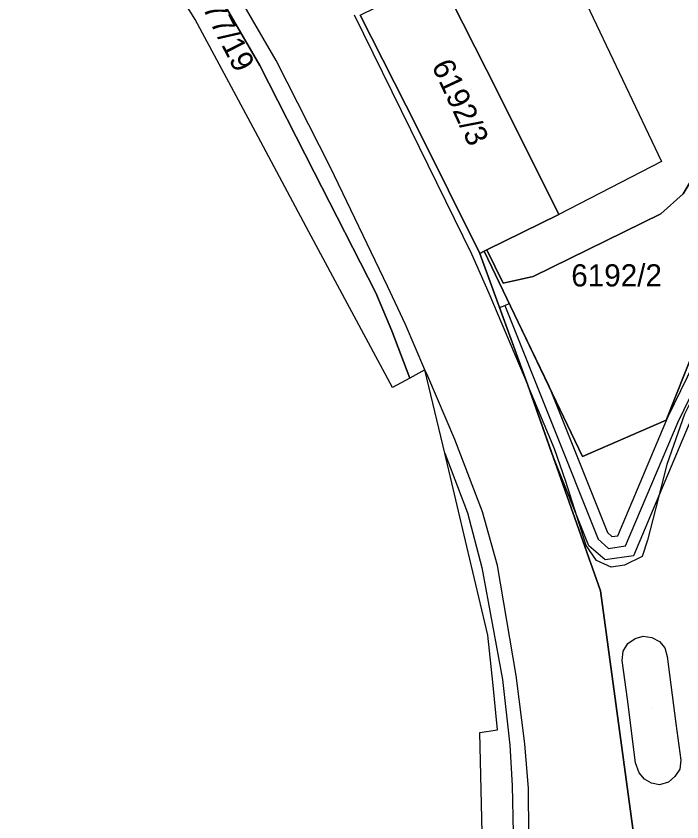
# Model space of a CAD drawing. Extents: x -266199 to -261993, y -1239047 to -1235108.
# Drawn here: x -264045.7 to -263985.6, y -1235963.6 to -1235890.9 of the extents above; entities that cross this region are included whole.
import ezdxf

# ---------------------------------------------------------------- set-up
doc = ezdxf.new("R2010")
doc.units = 0
for name, color, linetype in [('body_kn', 7, 'Continuous'), ('katuz_linie', 7, 'Continuous'), ('kladpar_druhypozemkov', 7, 'Continuous'), ('kladpar_hranice', 7, 'Continuous'), ('kladpar_parcelnecisla', 7, 'Continuous'), ('kladpar_plochy', 7, 'Continuous'), ('tarchy_linie', 7, 'Continuous'), ('zappar_hrandruhpozemk', 7, 'Continuous'), ('zuob_linie', 7, 'Continuous'), ('zuob_plochy', 7, 'Continuous')]:
    doc.layers.add(name, color=color, linetype=linetype)

msp = doc.modelspace()

# ---------------------------------------------------------------- linework, layer by layer
at = {"layer": 'body_kn'}
for p, q in [((-264029.57, -1235891.15), (-264029.57, -1235891.15)), ((-264023.75, -1235895.3), (-264023.75, -1235895.3)), ((-264022.25, -1235894.85), (-264022.25, -1235894.85)), ((-264002.2, -1235897.83), (-264002.2, -1235897.83)), ((-264010.15, -1235901.08), (-264010.15, -1235901.08)), ((-264009.53, -1235900.91), (-264009.53, -1235900.91)), ((-264024.13, -1235901.29), (-264024.13, -1235901.29)), ((-263987.47, -1235903.97), (-263987.47, -1235903.97)), ((-264017.36, -1235904.51), (-264017.36, -1235904.51)), ((-264018.82, -1235904.93), (-264018.82, -1235904.93)), ((-263996.74, -1235908.75), (-263996.74, -1235908.75)), ((-263996.74, -1235908.75), (-263996.74, -1235908.75)), ((-263987.53, -1235908.7), (-263987.53, -1235908.7)), ((-264019.3, -1235910.3), (-264019.3, -1235910.3)), ((-264003.25, -1235911.94), (-264003.25, -1235911.94)), ((-264003.25, -1235911.94), (-264003.25, -1235911.94)), ((-264004.64, -1235912.3), (-264004.64, -1235912.3)), ((-264003.88, -1235912.26), (-264003.88, -1235912.26)), ((-264003.88, -1235912.26), (-264003.88, -1235912.26)), ((-264003.48, -1235912.06), (-264003.48, -1235912.06)), ((-264003.48, -1235912.06), (-264003.48, -1235912.06)), ((-264001.76, -1235914.93), (-264001.76, -1235914.93)), ((-263999.06, -1235914.35), (-263999.06, -1235914.35)), ((-264012.21, -1235915.22), (-264012.21, -1235915.22)), ((-264013.28, -1235915.83), (-264013.28, -1235915.83)), ((-264003.07, -1235915.84), (-264003.07, -1235915.84)), ((-264001.62, -1235916.97), (-264001.62, -1235916.97)), ((-264001.62, -1235916.97), (-264001.62, -1235916.97)), ((-264001.22, -1235916.78), (-264001.22, -1235916.78)), ((-264001.22, -1235916.78), (-264001.22, -1235916.78)), ((-264002.1, -1235917.15), (-264002.1, -1235917.15)), ((-264011.83, -1235919.25), (-264011.83, -1235919.25)), ((-264010.6, -1235918.68), (-264010.6, -1235918.68)), ((-264008.83, -1235922.76), (-264008.83, -1235922.76)), ((-264010.21, -1235923.51), (-264010.21, -1235923.51)), ((-264010.21, -1235923.51), (-264010.21, -1235923.51)), ((-264008.56, -1235923.35), (-264008.56, -1235923.35)), ((-264011.76, -1235924.36), (-264011.76, -1235924.36)), ((-263999.56, -1235924.14), (-263999.56, -1235924.14)), ((-263997.66, -1235924.21), (-263997.66, -1235924.21)), ((-263986.9, -1235927.03), (-263986.9, -1235927.03)), ((-263987.05, -1235927.32), (-263987.05, -1235927.32)), ((-263985.99, -1235927.45), (-263985.99, -1235927.45)), ((-264006.14, -1235929.04), (-264006.14, -1235929.04)), ((-263997.44, -1235930.13), (-263997.44, -1235930.13)), ((-263997.15, -1235929.88), (-263997.15, -1235929.88)), ((-264007.04, -1235930.29), (-264007.04, -1235930.29)), ((-264007.04, -1235930.29), (-264007.04, -1235930.29)), ((-263994.6, -1235930.59), (-263994.6, -1235930.59)), ((-263987.01, -1235931.31), (-263987.01, -1235931.31)), ((-263996.11, -1235932.85), (-263996.11, -1235932.85)), ((-263987.98, -1235935.23), (-263987.98, -1235935.23)), ((-264005, -1235935.66), (-264005, -1235935.66)), ((-264003.63, -1235935.59), (-264003.63, -1235935.59)), ((-263995.11, -1235935.97), (-263995.11, -1235935.97)), ((-263992.36, -1235937.45), (-263992.36, -1235937.45)), ((-263993.2, -1235938.05), (-263993.2, -1235938.05)), ((-263991.95, -1235937.81), (-263991.95, -1235937.81)), ((-263991.42, -1235937.73), (-263991.42, -1235937.73)), ((-263988.74, -1235938.14), (-263988.74, -1235938.14)), ((-264005.04, -1235938.71), (-264005.04, -1235938.71)), ((-263994.28, -1235938.6), (-263994.28, -1235938.6)), ((-263994.04, -1235938.64), (-263994.04, -1235938.64)), ((-263992.27, -1235938.87), (-263992.27, -1235938.87)), ((-263990.72, -1235938.64), (-263990.72, -1235938.64)), ((-263990.01, -1235939.54), (-263990.01, -1235939.54)), ((-263989.22, -1235939.6), (-263989.22, -1235939.6)), ((-263993.36, -1235939.96), (-263993.36, -1235939.96)), ((-263992.58, -1235939.92), (-263992.58, -1235939.92)), ((-263990.81, -1235940.38), (-263990.81, -1235940.38)), ((-264003.71, -1235940.6), (-264003.71, -1235940.6)), ((-264002.28, -1235940.41), (-264002.28, -1235940.41)), ((-263992.02, -1235940.57), (-263992.02, -1235940.57)), ((-263993, -1235942.71), (-263993, -1235942.71)), ((-264003.15, -1235946.69), (-264003.15, -1235946.69)), ((-263989.13, -1235946.79), (-263989.13, -1235946.79)), ((-263988.36, -1235946.91), (-263988.36, -1235946.91)), ((-263990.53, -1235947.46), (-263990.53, -1235947.46)), ((-263989.87, -1235946.99), (-263989.87, -1235946.99)), ((-263987.66, -1235947.28), (-263987.66, -1235947.28)), ((-263990.93, -1235948.14), (-263990.93, -1235948.14)), ((-263987.19, -1235947.86), (-263987.19, -1235947.86)), ((-263991.03, -1235948.98), (-263991.03, -1235948.98)), ((-263986.96, -1235948.62), (-263986.96, -1235948.62)), ((-263986.96, -1235948.62), (-263986.96, -1235948.62)), ((-264000.6, -1235950.35), (-264000.6, -1235950.35)), ((-264002.71, -1235950.93), (-264002.71, -1235950.93)), ((-264001.84, -1235950.69), (-264001.84, -1235950.69)), ((-263990.55, -1235952.48), (-263990.55, -1235952.48)), ((-263986.2, -1235954.66), (-263986.2, -1235954.66)), ((-264003.87, -1235955.49), (-264003.87, -1235955.49)), ((-264002.27, -1235955.24), (-264002.27, -1235955.24)), ((-264001.16, -1235956.64), (-264001.16, -1235956.64)), ((-263999.83, -1235956.51), (-263999.83, -1235956.51)), ((-263989.82, -1235958.23), (-263989.82, -1235958.23)), ((-263985.75, -1235957.99), (-263985.75, -1235957.99)), ((-263989.5, -1235959.12), (-263989.5, -1235959.12)), ((-263985.84, -1235958.78), (-263985.84, -1235958.78)), ((-263989.01, -1235959.71), (-263989.01, -1235959.71)), ((-263986.85, -1235959.97), (-263986.85, -1235959.97)), ((-263986.27, -1235959.45), (-263986.27, -1235959.45)), ((-264000.95, -1235960.27), (-264000.95, -1235960.27)), ((-263999.49, -1235960.54), (-263999.49, -1235960.54)), ((-263988.39, -1235960.07), (-263988.39, -1235960.07)), ((-263987.66, -1235960.21), (-263987.66, -1235960.21))]:
    msp.add_line(p, q, dxfattribs=at)
at = {"layer": 'katuz_linie'}
msp.add_lwpolyline([(-264003.46, -1235973.59), (-264003.87, -1235955.49), (-264002.27, -1235955.24), (-264002.71, -1235950.93), (-264003.15, -1235946.69), (-264005.04, -1235938.71), (-264007.04, -1235930.29), (-264008.83, -1235922.76), (-264010.21, -1235923.51), (-264011.76, -1235924.36), (-264019.3, -1235910.3), (-264024.13, -1235901.29), (-264029.57, -1235891.15), (-264042.7, -1235869.88), (-264048.1, -1235861.33), (-264049.44, -1235859.21), (-264053.95, -1235852.08), (-264058.96, -1235845.12), (-264074.52, -1235819.37), (-264076.7, -1235814.88), (-264087.74, -1235792.21), (-264102.26, -1235766.16)], dxfattribs=at)
at = {"layer": 'kladpar_druhypozemkov'}
for p, q in [((-264004.59, -1235897.48), (-264004.59, -1235897.48)), ((-263990.87, -1235913.71), (-263990.87, -1235913.71)), ((-263988.31, -1235953.33), (-263988.31, -1235953.33))]:
    msp.add_line(p, q, dxfattribs=at)
at = {"layer": 'kladpar_hranice'}
msp.add_line((-264003.88, -1235912.26), (-264003.48, -1235912.06), dxfattribs=at)
for points in [[(-264010.21, -1235923.51), (-264011.76, -1235924.36), (-264019.3, -1235910.3), (-264024.13, -1235901.29), (-264029.57, -1235891.15), (-264042.7, -1235869.88), (-264048.1, -1235861.33), (-264045.58, -1235859.69), (-264045.03, -1235860.56), (-264029.32, -1235885.64), (-264023.75, -1235895.3), (-264018.82, -1235904.93), (-264013.28, -1235915.83), (-264011.83, -1235919.25), (-264010.21, -1235923.51)], [(-263967.09, -1235866.15), (-263961.68, -1235863.33), (-263976.83, -1235901.55), (-263987.05, -1235927.32), (-263994.6, -1235930.59), (-264003.48, -1235912.06)], [(-264003.48, -1235912.06), (-264003.25, -1235911.94), (-264001.76, -1235914.93), (-263999.06, -1235914.35), (-263987.53, -1235908.7), (-263985.53, -1235906.88), (-263984.68, -1235905.46), (-263980.84, -1235901.06), (-263967.09, -1235866.15)], [(-263967.09, -1235866.15), (-263980.84, -1235901.06), (-263984.68, -1235905.46), (-263985.53, -1235906.88), (-263987.53, -1235908.7), (-263999.06, -1235914.35), (-264001.76, -1235914.93), (-264003.25, -1235911.94)], [(-264003.46, -1235973.59), (-264003.87, -1235955.49), (-264002.27, -1235955.24), (-264002.71, -1235950.93), (-264003.15, -1235946.69), (-264005.04, -1235938.71), (-264007.04, -1235930.29), (-264008.83, -1235922.76), (-264010.21, -1235923.51), (-264011.83, -1235919.25), (-264013.28, -1235915.83), (-264018.82, -1235904.93), (-264023.75, -1235895.3), (-264029.32, -1235885.64)], [(-263996.74, -1235908.75), (-264003.25, -1235911.94), (-264003.48, -1235912.06), (-264003.88, -1235912.26), (-264009.53, -1235900.91), (-264014.69, -1235890.75), (-264007.55, -1235887.24), (-264002.2, -1235897.83), (-263996.74, -1235908.75)], [(-264003.25, -1235911.94), (-263996.74, -1235908.75), (-264002.2, -1235897.83), (-264007.55, -1235887.24)], [(-264014.69, -1235890.75), (-264009.53, -1235900.91), (-264003.88, -1235912.26)], [(-264003.48, -1235912.06), (-263994.6, -1235930.59), (-263987.05, -1235927.32), (-263976.83, -1235901.55)], [(-264003.88, -1235912.26), (-263999.56, -1235924.14), (-263993, -1235942.71), (-263989.54, -1235968.11), (-263988.96, -1235971.46)], [(-263988.96, -1235971.46), (-263989.54, -1235968.11), (-263993, -1235942.71), (-263999.56, -1235924.14), (-264003.88, -1235912.26)]]:
    msp.add_lwpolyline(points, dxfattribs=at)
at = {"layer": 'kladpar_plochy'}
for points in [[(-264010.21, -1235923.51), (-264011.76, -1235924.36), (-264019.3, -1235910.3), (-264024.13, -1235901.29), (-264029.57, -1235891.15), (-264042.7, -1235869.88), (-264048.1, -1235861.33), (-264045.58, -1235859.69), (-264045.03, -1235860.56), (-264029.32, -1235885.64), (-264023.75, -1235895.3), (-264018.82, -1235904.93), (-264013.28, -1235915.83), (-264011.83, -1235919.25)], [(-264003.48, -1235912.06), (-264003.25, -1235911.94), (-264001.76, -1235914.93), (-263999.06, -1235914.35), (-263987.53, -1235908.7), (-263985.53, -1235906.88), (-263984.68, -1235905.46), (-263980.84, -1235901.06), (-263967.09, -1235866.15), (-263961.68, -1235863.33), (-263976.83, -1235901.55), (-263987.05, -1235927.32), (-263994.6, -1235930.59)], [(-264003.25, -1235911.94), (-263996.74, -1235908.75), (-264002.2, -1235897.83), (-264007.55, -1235887.24), (-263997.85, -1235882.18), (-263967.09, -1235866.15), (-263980.84, -1235901.06), (-263984.68, -1235905.46), (-263985.53, -1235906.88), (-263987.53, -1235908.7), (-263999.06, -1235914.35), (-264001.76, -1235914.93)], [(-263996.74, -1235908.75), (-264003.25, -1235911.94), (-264003.48, -1235912.06), (-264003.88, -1235912.26), (-264009.53, -1235900.91), (-264014.69, -1235890.75), (-264007.55, -1235887.24), (-264002.2, -1235897.83)]]:
    msp.add_lwpolyline(points, close=True, dxfattribs=at)
for points in [[(-264003.46, -1235973.59), (-264003.87, -1235955.49), (-264002.27, -1235955.24), (-264002.71, -1235950.93), (-264003.15, -1235946.69), (-264005.04, -1235938.71), (-264007.04, -1235930.29), (-264008.83, -1235922.76), (-264010.21, -1235923.51), (-264011.83, -1235919.25), (-264013.28, -1235915.83), (-264018.82, -1235904.93), (-264023.75, -1235895.3), (-264029.32, -1235885.64)], [(-264014.69, -1235890.75), (-264009.53, -1235900.91), (-264003.88, -1235912.26), (-263999.56, -1235924.14), (-263993, -1235942.71), (-263989.54, -1235968.11)], [(-263989.54, -1235968.11), (-263993, -1235942.71), (-263999.56, -1235924.14), (-264003.88, -1235912.26), (-264003.48, -1235912.06), (-263994.6, -1235930.59), (-263987.05, -1235927.32), (-263976.83, -1235901.55), (-263973.05, -1235902.01), (-263965.79, -1235902.89), (-263963.69, -1235903.15), (-263955.45, -1235904.15), (-263972.24, -1235928.36), (-263966.53, -1235943.87), (-263967.21, -1235944.04), (-263972.02, -1235945.77), (-263967.64, -1235962.02), (-263961.65, -1235978.64)]]:
    msp.add_lwpolyline(points, dxfattribs=at)
at = {"layer": 'tarchy_linie'}
for points in [[(-264001.22, -1235916.78), (-263997.66, -1235924.21), (-263992.36, -1235937.45), (-263991.95, -1235937.81), (-263991.42, -1235937.73), (-263986.9, -1235927.03), (-263969.09, -1235890.51), (-263968.2, -1235890.95), (-263967.3, -1235891.38), (-263985.07, -1235927.86), (-263990.01, -1235939.54), (-263992.58, -1235939.92), (-263994.04, -1235938.64), (-263997.44, -1235930.13), (-263999.56, -1235924.14), (-264002.1, -1235917.15), (-264001.62, -1235916.97), (-264001.22, -1235916.78)], [(-264001.62, -1235916.97), (-263993.2, -1235938.05), (-263992.27, -1235938.87), (-263990.72, -1235938.64), (-263985.99, -1235927.45), (-263968.2, -1235890.95)]]:
    msp.add_lwpolyline(points, dxfattribs=at)
at = {"layer": 'zappar_hrandruhpozemk'}
for p, q in [((-263997.85, -1235882.18), (-263987.47, -1235903.97)), ((-264022.25, -1235894.85), (-264028.14, -1235884.74)), ((-264015.23, -1235890.73), (-264010.15, -1235901.08)), ((-263987.47, -1235903.97), (-263996.74, -1235908.75)), ((-263997.15, -1235929.88), (-263999.56, -1235924.14)), ((-264003.63, -1235935.59), (-264006.14, -1235929.04)), ((-263996.11, -1235932.85), (-263997.15, -1235929.88)), ((-263986.96, -1235948.62), (-263986.2, -1235954.66)), ((-263989.82, -1235958.23), (-263990.55, -1235952.48))]:
    msp.add_line(p, q, dxfattribs=at)
for points in [[(-264006.14, -1235929.04), (-264008.56, -1235923.35), (-264008.83, -1235922.76), (-264010.6, -1235918.68), (-264012.21, -1235915.22), (-264017.36, -1235904.51), (-264022.25, -1235894.85)], [(-264010.15, -1235901.08), (-264004.64, -1235912.3), (-264003.07, -1235915.84), (-263999.56, -1235924.14)], [(-263983.84, -1235923.64), (-263985.39, -1235926.77), (-263987.01, -1235931.31), (-263987.98, -1235935.23), (-263988.74, -1235938.14), (-263989.22, -1235939.6), (-263990.81, -1235940.38), (-263992.02, -1235940.57), (-263993.36, -1235939.96), (-263994.28, -1235938.6), (-263995.11, -1235935.97), (-263996.11, -1235932.85)], [(-264007.04, -1235930.29), (-264005, -1235935.66), (-264003.71, -1235940.6), (-264001.84, -1235950.69), (-264001.16, -1235956.64), (-264000.95, -1235960.27), (-264000.88, -1235964.55), (-264001.01, -1235967.61)], [(-264015.3, -1236019.75), (-264011.9, -1236003.88), (-264008, -1235990.6), (-264001.33, -1235976.92), (-263999.63, -1235968), (-263999.45, -1235964.66), (-263999.49, -1235960.54), (-263999.83, -1235956.51), (-264000.6, -1235950.35), (-264002.28, -1235940.41), (-264003.63, -1235935.59)], [(-263990.55, -1235952.48), (-263991.03, -1235948.98), (-263990.93, -1235948.14), (-263990.53, -1235947.46), (-263989.87, -1235946.99), (-263989.13, -1235946.79), (-263988.36, -1235946.91), (-263987.66, -1235947.28), (-263987.19, -1235947.86), (-263986.96, -1235948.62)], [(-263986.2, -1235954.66), (-263985.75, -1235957.99), (-263985.84, -1235958.78), (-263986.27, -1235959.45), (-263986.85, -1235959.97), (-263987.66, -1235960.21), (-263988.39, -1235960.07), (-263989.01, -1235959.71), (-263989.5, -1235959.12), (-263989.82, -1235958.23)]]:
    msp.add_lwpolyline(points, dxfattribs=at)
at = {"layer": 'zuob_linie'}
msp.add_lwpolyline([(-264003.46, -1235973.59), (-264003.87, -1235955.49), (-264002.27, -1235955.24), (-264002.71, -1235950.93), (-264003.15, -1235946.69), (-264005.04, -1235938.71), (-264007.04, -1235930.29), (-264008.83, -1235922.76), (-264010.21, -1235923.51), (-264011.76, -1235924.36), (-264019.3, -1235910.3), (-264024.13, -1235901.29), (-264029.57, -1235891.15), (-264042.7, -1235869.88)], dxfattribs=at)
at = {"layer": 'zuob_plochy'}
msp.add_lwpolyline([(-264003.46, -1235973.59), (-264003.87, -1235955.49), (-264002.27, -1235955.24), (-264002.71, -1235950.93), (-264003.15, -1235946.69), (-264005.04, -1235938.71), (-264007.04, -1235930.29), (-264008.83, -1235922.76), (-264010.21, -1235923.51), (-264011.76, -1235924.36), (-264019.3, -1235910.3), (-264024.13, -1235901.29), (-264029.57, -1235891.15), (-264042.7, -1235869.88)], dxfattribs=at)

# ---------------------------------------------------------------- texts
at = {"layer": 'kladpar_parcelnecisla'}
for s, rotation, p in [('8277/19', 297, (-264030.286, -1235887.444)), ('6192/3', 295, (-264008.263, -1235895.317))]:
    msp.add_text(s, height=2, rotation=rotation, dxfattribs=at).set_placement(p)
msp.add_text('6192/2', height=2, dxfattribs=at).set_placement((-263995.624, -1235915.24))

doc.saveas('drawing.dxf')
